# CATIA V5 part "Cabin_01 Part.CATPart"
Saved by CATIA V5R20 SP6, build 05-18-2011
Part number: Cabin_01 Part
Bounding box of the stored display mesh (mm): x -71.5 to 71.5, y -100 to 40, z 20 to 265
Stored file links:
  E:\#01 CATIA Lecture Materials\#06 DMU\#01 DMU KIN Page01 EX01\#01 CATPart\Cabin_01 Part.CATPart
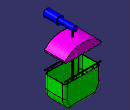
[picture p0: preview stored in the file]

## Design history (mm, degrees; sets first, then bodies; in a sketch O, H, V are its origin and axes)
Body1 (main body)
Body2
  Body3
    Sketch1 on zx-plane, origin (0, 0, 0), H (-1, 0, 0), V (0, 0, 1)
      line L1 (70.0001, 110) -> (-69.9999, 110)
      point P1 (70.0001, 110)
      point P2 (-69.9999, 110)
      line L2 (-69.9999, 60) -> (-69.9999, 110)
      point P3 (-69.9999, 60)
      point P4 (-69.9999, 110)
      arc A1 centre (-19.9999, 60) radius 50 from (-69.9999, 60) to (-49.9999, 20) ccw
      point P5 (-69.9999, 60)
      point P6 (-49.9999, 20)
      line L3 (50.0001, 20) -> (-49.9999, 20)
      point P7 (50.0001, 20)
      point P8 (-49.9999, 20)
      arc A2 centre (20.0001, 60) radius 50 from (50.0001, 20) to (70.0001, 60) ccw
      point P9 (50.0001, 20)
      point P10 (70.0001, 60)
      line L4 (70.0001, 60) -> (70.0001, 110)
      point P11 (70.0001, 60)
      point P12 (70.0001, 110)
      coincidence: P1 P12, P2 P4, P3 P5, P6 P8, P7 P9, P10 P11
    Pad1: profile Sketch1, direction (0, 1, 0), length 40, mirrored extent
    Fillet1: radius 10, on edge [face of Pad1 from Sketch1.L2 | end face of Pad1]; edge [face of Pad1 from Sketch1.L4 | end face of Pad1]; edge [face of Pad1 from Sketch1.L3 | end face of Pad1]; edge [face of Pad1 from Sketch1.L3 | face of Pad1 from Sketch1.A1]; edge [start face of Pad1 | face of Pad1 from Sketch1.L3]; edge [face of Pad1 from Sketch1.A2 | face of Pad1 from Sketch1.L3]; edge [start face of Pad1 | face of Pad1 from Sketch1.A1]; edge [start face of Pad1 | face of Pad1 from Sketch1.A2]
    Shell1: ExtOffset 0, Face face of Pad1 from Sketch1.L1, IntOffset 2
  Assemble1: tool Body3
  Body4
    Sketch2 on zx-plane, origin (0, 0, 0), H (-1, 0, 0), V (0, 0, 1)
      line L1 (59.6546, 110) -> (56.6546, 110)
      line L2 (70.0001, 123) -> (-69.9999, 123)
      line L3 (-40.9999, 120) -> (-57.0094, 120)
      line L4 (-1.4999, 120) -> (-37.9999, 120)
      line L5 (38.0001, 120) -> (1.5001, 120)
      line L6 (70.0001, 120) -> (59.6546, 120)
      arc A1 centre (70.0001, 121.5) radius 1.5 from (70.0001, 120) to (70.0001, 123) ccw
      arc A2 centre (-69.9999, 121.5) radius 1.5 from (-69.9999, 123) to (-69.9999, 120) ccw
      line L7 (-40.9999, 120) -> (-40.9999, 110)
      line L8 (-37.9999, 120) -> (-37.9999, 110)
      line L9 (-1.4999, 120) -> (-1.4999, 110)
      line L10 (1.5001, 120) -> (1.5001, 110)
      line L11 (38.0001, 120) -> (38.0001, 110)
      line L12 (41.0001, 120) -> (41.0001, 110)
      line L13 (-60.0094, 110) -> (-60.0094, 120)
      point P23 (-60.0094, 110)
      point P24 (-60.0094, 120)
      line L14 (-57.0094, 110) -> (-57.0094, 120)
      point P25 (-57.0094, 110)
      point P26 (-57.0094, 120)
      line L15 (59.6546, 110) -> (59.6546, 120)
      point P27 (59.6546, 110)
      point P28 (59.6546, 120)
      line L16 (56.6546, 110) -> (56.6546, 120)
      point P30 (56.6546, 120)
      point P33 (-57.0094, 120)
      line L17 (-60.0094, 120) -> (-69.9999, 120)
      point P34 (59.6546, 120)
      line L18 (56.6546, 120) -> (41.0001, 120)
      point P35 (59.6546, 110)
      line L19 (41.0001, 110) -> (38.0001, 110)
      point P36 (41.0001, 110)
      point P37 (38.0001, 110)
      line L20 (1.5001, 110) -> (-1.4999, 110)
      point P38 (1.5001, 110)
      point P39 (-1.4999, 110)
      line L21 (-37.9999, 110) -> (-40.9999, 110)
      point P40 (-37.9999, 110)
      point P41 (-40.9999, 110)
      line L22 (-60.0094, 110) -> (-57.0094, 110)
      distance L13 L14 = 3
      distance L15 L16 = 3
      coincidence: P23 L1, P24 L3, P25 L1, P26 L3, P27 L1, P28 L6, P30 L6, L14 P33, L3 L17, L15 P34, L6 L18, L15 P35, L12 P36, L1 L19, L11 P37, L10 P38, L19 L20, L9 P39, L8 P40, L20 L21, L7 P41
      vertical: L13 V, L14 V, L15 V, L16 V
      horizontal: L22 H
    Pad2: profile Sketch2, direction (0, 1, 0), length 40, opposite side length -38
    Mirror1: of the body so far, about zx-plane
  Assemble2: tool Body4
  Body5
    Sketch3 on zx-plane, origin (0, 0, 0), H (-1, 0, 0), V (0, 0, 1)
      arc A1 centre (0.0001, 123.3333) radius 96.6667 from (70.0001, 190) to (-69.9999, 190) ccw
      line L1 (-69.9999, 185) -> (-69.9999, 190)
      arc A2 centre (-63.6362, 187.9162) radius 7 from (-69.9999, 185) to (-57.2726, 185) ccw
      arc A3 centre (-50.909, 187.9162) radius 7 from (-57.2726, 185) to (-44.5453, 185) ccw
      arc A4 centre (-38.1817, 187.9162) radius 7 from (-44.5453, 185) to (-31.8181, 185) ccw
      arc A5 centre (-25.4544, 187.9162) radius 7 from (-31.8181, 185) to (-19.0908, 185) ccw
      arc A6 centre (-12.7272, 187.9162) radius 7 from (-19.0908, 185) to (-6.3635, 185) ccw
      arc A7 centre (0.0001, 187.9162) radius 7 from (-6.3635, 185) to (6.3638, 185) ccw
      arc A8 centre (12.7274, 187.9162) radius 7 from (6.3638, 185) to (19.091, 185) ccw
      arc A9 centre (25.4547, 187.9162) radius 7 from (19.091, 185) to (31.8183, 185) ccw
      arc A10 centre (38.1819, 187.9162) radius 7 from (31.8183, 185) to (44.5456, 185) ccw
      arc A11 centre (50.9092, 187.9162) radius 7 from (44.5456, 185) to (57.2728, 185) ccw
      arc A12 centre (63.6365, 187.9162) radius 7 from (57.2728, 185) to (70.0001, 185) ccw
      line L2 (70.0001, 185) -> (70.0001, 190)
    Pad3: profile Sketch3, direction (0, 1, 0), length 40, mirrored extent
    Shell2: ExtOffset 0, Face (face of Pad3 from Sketch3.A2; face of Pad3 from Sketch3.A3; face of Pad3 from Sketch3.A4; face of Pad3 from Sketch3.A5; face of Pad3 from Sketch3.A6; face of Pad3 from Sketch3.A7; face of Pad3 from Sketch3.A8; face of Pad3 from Sketch3.A9; face of Pad3 from Sketch3.A10; face of Pad3 from Sketch3.A11; face of Pad3 from Sketch3.A12), IntOffset 1
  Assemble3: tool Body5
  Body6
    Sketch4 on zx-plane, origin (0, 0, 0), H (-1, 0, 0), V (0, 0, 1)
      line L1 (-2.9999, 240.4606) -> (-2.9999, 20)
      line L2 (3.0001, 240.4606) -> (3.0001, 20)
      line L3 (3.0001, 20) -> (-2.9999, 20)
      arc A1 centre (0.0001, 250) radius 10 from (-2.9999, 240.4606) to (3.0001, 240.4606) ccw
    Pad4: profile Sketch4, direction (0, 1, 0), length 3, mirrored extent
    Fillet2: radius 2, on edge [face of Pad4 from Sketch4.L1 | end face of Pad4]; edge [face of Pad4 from Sketch4.L2 | end face of Pad4]; edge [start face of Pad4 | face of Pad4 from Sketch4.L2]; edge [start face of Pad4 | face of Pad4 from Sketch4.L1]
  Assemble4: tool Body6
  Body7
    Sketch5 on zx-plane, origin (0, 0, 0), H (-1, 0, 0), V (0, 0, 1)
      circle A1 centre (0.0001, 250) radius 10
    Pad5: profile Sketch5, direction (0, -1, 0), length 80, opposite side length 10
  Assemble5: tool Body7
  Body8
    Sketch6 on zx-plane, origin (0, 0, 0), H (-1, 0, 0), V (0, 0, 1)
      circle A1 centre (0.0001, 250) radius 15
      radius A1 = 15
    Pad6: profile Sketch6, direction (0, -1, 0), length 100, opposite side length -50
  Assemble6: tool Body8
